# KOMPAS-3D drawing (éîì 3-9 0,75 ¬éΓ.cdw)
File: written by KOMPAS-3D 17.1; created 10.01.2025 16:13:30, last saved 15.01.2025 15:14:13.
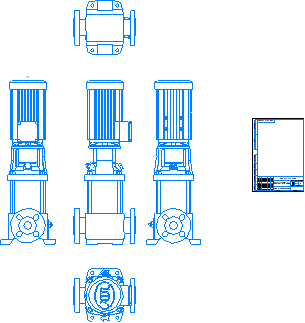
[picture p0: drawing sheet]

Sheet 1: A4, portrait

Title block, sheet 1: name: ВМН 3-9 0,75 кВт; designation: ВМН 3-9 0,75 кВт; material: Сталь 10  ГОСТ 1050-2013; mass: 68,16; sheets: 1; sheet format: A4; stored path: \\adlc.lan\data\АДЛ_ПКД\3D-модели\ADL production\Насосы ГРАНПАМП\Насосы ВМН\ВМН3\KOMPAS 3D\3-9 0,75 кВт _ ВМН.cdw

Views: Вид 1, Спереди, Проекционный вид 2, Проекционный вид 3, Проекционный вид 4, Проекционный вид 5
Referenced files in \\adlc.lan\data\АДЛ_ПКД\3D-модели\ADL production\Насосы ГРАНПАМП\Насосы ВМН\ВМН3\KOMPAS 3D\: ВМН 3-9 0,75 кВт.m3d
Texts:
  Andrey
  АДЛ
Dimensions and other numbers on the sheet: 1:1; 1; 68,16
